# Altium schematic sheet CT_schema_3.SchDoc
size 187 x 159 mm
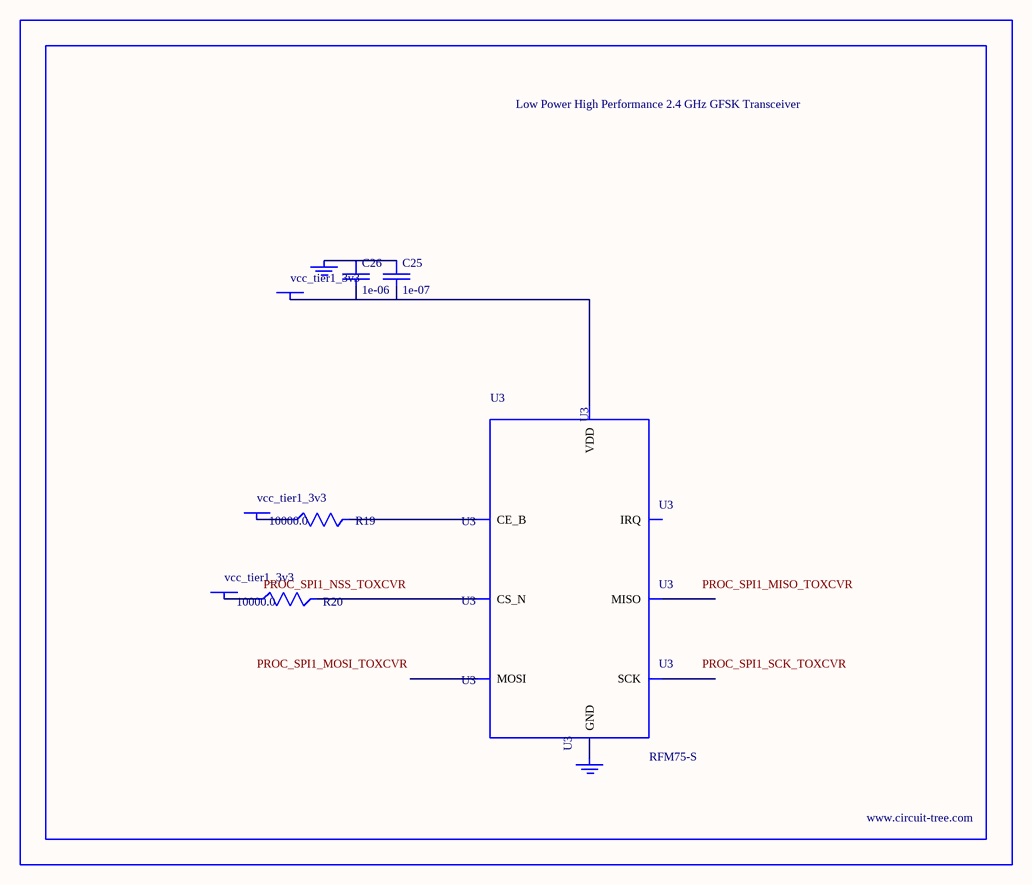
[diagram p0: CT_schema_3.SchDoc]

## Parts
BORDER2  (no value)
C25  1e-07  [C0402]
C26  1e-06  [C0603]
GND_INSTANCE_2_0  (no value)
GND_INSTANCE_2_1  (no value)
POWER_INSTANCE_2_0  vcc_tier1_3v3
POWER_INSTANCE_2_1  vcc_tier1_3v3
POWER_INSTANCE_2_2  vcc_tier1_3v3
R19  10000.0  [R0603]
R20  10000.0  [R0603]
U3  RFM75-S  [RFM75-S]

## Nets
NetC25_1: C25.1 C26.1 GND_INSTANCE_2_0.0(GND)
NetC25_2: C25.2 C26.2 POWER_INSTANCE_2_0.0(PWR) U3.2(VDD)
NetGND_INSTANCE_2_1_0: GND_INSTANCE_2_1.0(GND) U3.1(GND)
NetPOWER_INSTANCE_2_1_0: POWER_INSTANCE_2_1.0(PWR) R19.1
NetPOWER_INSTANCE_2_2_0: POWER_INSTANCE_2_2.0(PWR) R20.1
NetR19_2: R19.2 U3.3(CE_B)
NetR20_2: R20.2 U3.4(CS_N)

Not connected (* = marked no-connect by the designer): U3 5(SCK) 6(MOSI) 7(MISO) 8(IRQ)

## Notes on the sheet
- Labels drawn without touching a wire or pin: PROC_SPI1_MISO_TOXCVR, PROC_SPI1_MOSI_TOXCVR, PROC_SPI1_NSS_TOXCVR, PROC_SPI1_SCK_TOXCVR

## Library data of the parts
BORDER2 = BORDER_PAGE2
C25 = C0402C104K3RACTU
C26 = C0603C105K3RACTU
GND_INSTANCE_2_0 GND_INSTANCE_2_1 = GND
POWER_INSTANCE_2_0-POWER_INSTANCE_2_2 = PWR
R19 R20 = RC0603JR-0710KL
